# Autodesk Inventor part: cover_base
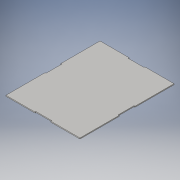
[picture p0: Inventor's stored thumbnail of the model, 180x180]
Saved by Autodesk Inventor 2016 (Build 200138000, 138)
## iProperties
Created: 2015-11
Part Number: cover_base
Material: Generic
Document SubType Name: Modeling
Designer: silverd
Density: 1 g/cm^3
Appearance: Default
Author: silverd
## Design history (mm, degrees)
sketch "Sketch1"
  geometry: L1 (0, 0)-(91.887, 0); L2 (234.194, 0)-(234.194, -123.637); L3 (234.194, -297.694)-(142.306, -297.694); L4 (0, -297.694)-(0, -174.056); L5 (91.887, 0)-(91.887, -3); L6 (91.887, -3)-(142.306, -3); L7 (142.306, -3)-(142.306, 0); L8 (142.306, -294.694)-(91.887, -294.694); L9 (91.887, -294.694)-(91.887, -297.694); L10 (142.306, -297.694)-(142.306, -294.694); L11 (231.194, -123.637)-(231.194, -174.056); L12 (231.194, -174.056)-(234.194, -174.056); L13 (234.194, -123.637)-(231.194, -123.637); L14 (3, -174.056)-(3, -123.637); L15 (3, -123.637)-(0, -123.637); L16 (0, -174.056)-(3, -174.056); L17 (142.306, 0)-(234.194, 0); L18 (0, -123.637)-(0, 0); L19 (91.887, -297.694)-(0, -297.694); L20 (234.194, -174.056)-(234.194, -297.694); 12 further points
  constraints: 40 end point, 12 parallel, 7 perpendicular, 4 midpoint, 3 horizontal
  dimensions: "d0" = 234.1936 distance of L3.start L4.start (= cover_w + 2 x acrylic); "d1" = 297.6936 distance of L2.start L3.start (= cover_l + 2 x acrylic); "d2" = 50.419 distance of L6.end L5.end (= tab_w - t); "d3" = 3 distance of L5.end L1.end (= acrylic); "d4" = 50.419 distance of L3.end L9.end (= d7 - d8); "d5" = 3 distance of L9.end L8.end (= d6); "d9" = 50.419 distance of L2.end L12.end (= d12 - d13); "d10" = 3 distance of L12.end L11.end (= d11); "d14" = 50.419 distance of L4.end L15.end (= d17 - d18); "d15" = 3 distance of L15.end L14.end (= d16); "d21" = 123.6373 distance of L2.start L2.end; "d22" = 123.6373 distance of L12.end L3.start; "d23" = 123.6373 distance of L15.end L1.start; "d24" = 123.6373 distance of L4.start L4.end; "d25" = 91.8873 distance of L3.start L3.end; "d26" = 91.8873 distance of L9.end L4.start; "d27" = 91.8873 distance of L7.end L2.start
extrude "Extrusion1" new body sketch "Sketch1" distance "d19" = 3 (= acrylic); taper "d20" = 0 deg
body "Solid1"
other parameters: "cover_w" = 228.1936 [user parameter; used in 1 equation term], "cover_l" = 291.6936 [user parameter; used in 1 equation term], "tab_w" = 50.8 [user parameter; used in 1 equation term], "acrylic" = 3 [user parameter; used in 4 equation terms], "t" = 0.381 [user parameter; used in 1 equation term], "d6" = 3 [user parameter; used in 1 equation term], "d7" = 50.8 [user parameter; used in 1 equation term], "d8" = 0.381 [user parameter; used in 1 equation term], "d11" = 3 [user parameter; used in 1 equation term], "d12" = 50.8 [user parameter; used in 1 equation term], "d13" = 0.381 [user parameter; used in 1 equation term], "d16" = 3 [user parameter; used in 1 equation term], "d17" = 50.8 [user parameter; used in 1 equation term], "d18" = 0.381 [user parameter; used in 1 equation term]
